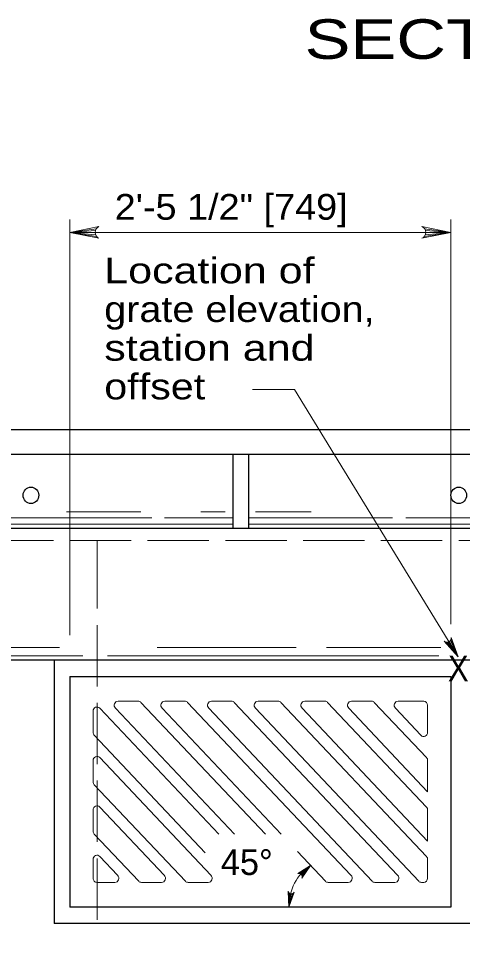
# Model space of a CAD drawing. Extents: x 1352.5 to 1386.5, y 735.9 to 779.9.
# Drawn here: x 1360.33 to 1363.03, y 762.99 to 768.66 of the extents above; entities that cross this region are included whole.
import ezdxf
from ezdxf.enums import TextEntityAlignment as Align

# ---------------------------------------------------------------- set-up
doc = ezdxf.new("R2010")
doc.units = 0
doc.header["$LTSCALE"] = 0.062
doc.linetypes.add('LONG_DASHED', pattern=[7.5, 6, -1.5])
doc.layers.add('1', color=7, linetype='Continuous', lineweight=13)

msp = doc.modelspace()

# ---------------------------------------------------------------- linework, layer by layer
at = {"layer": '1'}
for p, q in [((1360.64467, 764.92325), (1360.64467, 767.44517)), ((1362.9575, 764.99033), (1362.9575, 767.44517)), ((1360.80492, 767.38892), (1360.64467, 767.3665)), ((1360.7995, 767.37783), (1360.64467, 767.3665)), ((1362.79725, 767.38892), (1362.9575, 767.3665)), ((1362.80267, 767.37783), (1362.9575, 767.3665)), ((1360.64467, 767.3665), (1362.10425, 767.3665)), ((1360.79783, 767.3665), (1360.64467, 767.3665)), ((1360.80067, 767.35217), (1360.64467, 767.3665)), ((1360.80683, 767.34175), (1360.64467, 767.3665)), ((1362.10425, 767.3665), (1362.9575, 767.3665)), ((1362.79533, 767.34175), (1362.9575, 767.3665)), ((1362.8015, 767.35217), (1362.9575, 767.3665)), ((1362.80433, 767.3665), (1362.9575, 767.3665)), ((1360.62375, 765.672), (1361.07475, 765.672)), ((1361.43867, 765.672), (1361.58725, 765.672)), ((1361.77183, 765.672), (1362.11008, 765.672)), ((1360.17267, 765.63458), (1361.14133, 765.63458)), ((1361.21833, 765.63458), (1361.63583, 765.63458)), ((1361.73025, 765.63458), (1362.60208, 765.63458)), ((1362.68408, 765.63458), (1364.27908, 765.63458)), ((1360.17267, 765.59708), (1361.63583, 765.59708)), ((1361.73025, 765.59708), (1364.27908, 765.59708)), ((1362.9305, 764.88142), (1363.0005, 764.79217)), ((1362.93908, 764.88158), (1363.0005, 764.79217)), ((1362.94642, 764.88425), (1363.0005, 764.79217)), ((1362.95408, 764.89042), (1363.0005, 764.79217)), ((1362.95808, 764.89733), (1363.0005, 764.79217)), ((1359.91117, 764.8475), (1360.5815, 764.8475)), ((1361.17508, 764.8475), (1362.018, 764.8475)), ((1362.20208, 764.8475), (1362.89667, 764.8475)), ((1358.72892, 764.7975), (1360.724, 764.7975)), ((1360.87233, 764.7975), (1362.88475, 764.7975)), ((1361.54892, 763.71533), (1360.82658, 764.48008)), ((1361.64325, 763.71533), (1360.92092, 764.48008)), ((1360.93767, 764.52267), (1361.05975, 764.52267)), ((1361.83208, 763.71533), (1361.07642, 764.51533)), ((1361.92642, 763.71533), (1361.20417, 764.48008)), ((1361.22083, 764.52267), (1361.34292, 764.52267)), ((1362.35083, 763.466), (1361.35958, 764.51533)), ((1362.47858, 763.43067), (1361.48733, 764.48008)), ((1361.504, 764.52267), (1361.62608, 764.52267)), ((1362.634, 763.466), (1361.64283, 764.51533)), ((1362.76175, 763.43067), (1361.77058, 764.48008)), ((1361.78725, 764.52267), (1361.90933, 764.52267)), ((1362.80892, 763.58058), (1361.926, 764.51533)), ((1362.81583, 763.67317), (1362.05375, 764.48008)), ((1362.07042, 764.52267), (1362.1925, 764.52267)), ((1362.80892, 763.88042), (1362.20917, 764.51533)), ((1362.81583, 763.97308), (1362.33692, 764.48008)), ((1362.35367, 764.52267), (1362.47575, 764.52267)), ((1362.80892, 764.18025), (1362.49242, 764.51533)), ((1362.77558, 764.3155), (1362.62017, 764.48008)), ((1362.79225, 764.52267), (1362.63683, 764.52267)), ((1362.81583, 764.33317), (1362.81583, 764.49767)), ((1360.78625, 764.33317), (1360.78625, 764.46242)), ((1361.46625, 763.60292), (1360.79317, 764.3155)), ((1360.78625, 764.03333), (1360.78625, 764.16258)), ((1361.50117, 763.466), (1360.82658, 764.18025)), ((1362.81583, 763.97308), (1362.81583, 764.16258)), ((1361.34575, 763.43067), (1360.79317, 764.01567)), ((1360.78625, 763.7335), (1360.78625, 763.86275)), ((1361.218, 763.466), (1360.82658, 763.88042)), ((1362.81583, 763.67317), (1362.81583, 763.86275)), ((1361.06258, 763.43067), (1360.79317, 763.71583)), ((1360.93483, 763.466), (1360.82658, 763.58058)), ((1362.19533, 763.43067), (1362.02608, 763.60983)), ((1360.78625, 763.56292), (1360.78625, 763.44833)), ((1362.037, 763.47767), (1362.10475, 763.52658)), ((1362.04283, 763.47583), (1362.10475, 763.52658)), ((1362.04875, 763.47133), (1362.10475, 763.52658)), ((1362.052, 763.46633), (1362.10475, 763.52658)), ((1362.05383, 763.46017), (1362.10475, 763.52658)), ((1362.81583, 763.44833), (1362.81583, 763.56292)), ((1360.91808, 763.42333), (1360.80983, 763.42333)), ((1361.07925, 763.42333), (1361.20133, 763.42333)), ((1361.36242, 763.42333), (1361.4845, 763.42333)), ((1362.212, 763.42333), (1362.33408, 763.42333)), ((1362.49525, 763.42333), (1362.61733, 763.42333)), ((1362.77842, 763.42333), (1362.79225, 763.42333)), ((1361.97508, 763.359), (1361.97325, 763.27342)), ((1361.9985, 763.356), (1361.97325, 763.27342)), ((1361.98008, 763.35525), (1361.97325, 763.27342)), ((1361.99292, 763.35367), (1361.97325, 763.27342)), ((1361.98567, 763.35342), (1361.97325, 763.27342))]:
    msp.add_line(p, q, dxfattribs=at)
at = {"layer": '1', "lineweight": 25}
for p, q in [((1360.17267, 766.17175), (1365.83667, 766.17175)), ((1360.17267, 766.02183), (1365.83667, 766.02183)), ((1361.63583, 765.57208), (1361.63583, 766.02183)), ((1361.73025, 765.57208), (1361.73025, 766.02183)), ((1360.17267, 765.57208), (1365.83667, 765.57208)), ((1358.29033, 764.77258), (1364.77742, 764.77258)), ((1360.64467, 764.67258), (1360.64467, 763.27342)), ((1360.64467, 764.67258), (1362.9575, 764.67258)), ((1362.9575, 763.27342), (1360.64467, 763.27342))]:
    msp.add_line(p, q, dxfattribs=at)
at = {"layer": '1', "linetype": 'LONG_DASHED'}
msp.add_line((1360.17267, 765.49717), (1365.83667, 765.49717), dxfattribs=at)
at = {"layer": '1'}
for points in [[(1360.82167, 767.33108), (1360.64467, 767.3665), (1360.82167, 767.40192)], [(1362.7805, 767.33108), (1362.9575, 767.3665), (1362.7805, 767.40192)], [(1363.0005, 764.79217), (1362.00858, 766.413), (1361.75267, 766.413)], [(1362.95925, 764.90967), (1363.0005, 764.79217), (1362.91675, 764.88742)], [(1362.02783, 763.47642), (1362.10475, 763.52658), (1362.05208, 763.44908)], [(1362.00508, 763.36283), (1361.97325, 763.27342), (1361.97008, 763.36883)]]:
    msp.add_lwpolyline(points, dxfattribs=at)
at = {"layer": '1', "linetype": 'LONG_DASHED'}
msp.add_lwpolyline([(1360.80983, 765.49717), (1360.80983, 765.4565), (1360.80983, 763.1735)], dxfattribs=at)
at = {"layer": '1', "lineweight": 25}
for points in [[(1360.55025, 764.77258), (1360.55025, 763.81325), (1360.55025, 763.1735)], [(1362.9575, 764.67258), (1362.9575, 764.10783), (1362.9575, 763.27342)], [(1365.45908, 763.1735), (1363.63192, 763.1735), (1360.55025, 763.1735)]]:
    msp.add_lwpolyline(points, dxfattribs=at)
at = {"layer": '1'}
for centre, start, end in [((1360.83597, 767.36656), 112.08782, 247.91395), ((1362.76618, 767.36656), 292.08605, 67.91218)]:
    msp.add_arc(centre, 0.0382, start, end, dxfattribs=at)
at = {"layer": '1', "lineweight": 25}
for centre in [(1360.40867, 765.77197), (1363.00467, 765.77197)]:
    msp.add_ellipse(centre, major_axis=(0, 0.04997), ratio=0.944544, dxfattribs=at)
at = {"layer": '1'}
for centre, major_axis, start_param, end_param in [((1362.93293, 764.90715), (-0.0229, 0.01423), 1.4490743, 3.8196874), ((1360.80987, 764.46237), (0, 0.02499), 5.4977871, 7.8539816), ((1360.93765, 764.4977), (0, -0.02499), 3.1415927, 5.4977871), ((1361.0597, 764.4977), (0, 0.02499), 5.4977871, 6.2831853), ((1361.22085, 764.4977), (0, -0.02499), 3.1415927, 5.4977871), ((1361.3429, 764.4977), (0, 0.02499), 5.4977871, 6.2831853), ((1361.50405, 764.4977), (0, -0.02499), 3.1415927, 5.4977871), ((1361.6261, 764.4977), (0, 0.02499), 5.4977871, 6.2831853), ((1361.78725, 764.4977), (0, -0.02499), 3.1415927, 5.4977871), ((1361.9093, 764.4977), (0, 0.02499), 5.4977871, 6.2831853), ((1362.07045, 764.4977), (0, -0.02499), 3.1415927, 5.4977871), ((1362.1925, 764.4977), (0, 0.02499), 5.4977871, 6.2831853), ((1362.35366, 764.4977), (0, -0.02499), 3.1415927, 5.4978629), ((1362.4757, 764.4977), (0, 0.02499), 5.4977871, 6.2831853), ((1362.63685, 764.4977), (0, -0.02499), 3.1415927, 5.4977871), ((1362.79227, 764.4977), (0, 0.02499), 4.712389, 6.2831853), ((1360.80987, 764.33315), (0, 0.02499), 1.5707963, 2.3561945), ((1362.79227, 764.33315), (0, -0.02499), 5.4977871, 7.8539816), ((1360.80987, 764.16254), (0, 0.02499), 5.4977871, 7.8539816), ((1362.79227, 764.16254), (0, 0.02499), 4.712389, 5.4977871), ((1360.80987, 764.03333), (0, 0.02499), 1.5707963, 2.3561945), ((1360.80987, 763.86271), (0, 0.02499), 5.4977871, 7.8539816), ((1362.79227, 763.86271), (0, 0.02499), 4.712389, 5.4977871), ((1360.80987, 763.7335), (0, 0.02499), 1.5707963, 2.3561945), ((1360.80987, 763.56289), (0, 0.02499), 5.4977871, 7.8539816), ((1362.79227, 763.56289), (0, 0.02499), 4.712389, 5.4977871), ((1362.25647, 763.27341), (0, 0.29983), 0.565407, 1.5707963), ((1360.9181, 763.44831), (0, -0.02499), 6.2831853, 8.6393798), ((1361.2013, 763.44831), (0, -0.02499), 6.2831853, 8.6393798), ((1361.4845, 763.44831), (0, -0.02499), 6.2831853, 8.6393798), ((1362.03475, 763.45751), (0, -0.02022), 1.1360379, 3.506651), ((1362.3341, 763.44831), (0, -0.02499), 6.2831853, 8.6393798), ((1362.6173, 763.44831), (0, -0.02499), 6.2831853, 8.6393798), ((1360.80987, 763.44831), (0, 0.02499), 1.5707963, 3.1415927), ((1361.07925, 763.44831), (0, -0.02499), 5.4977871, 6.2831853), ((1361.36245, 763.44831), (0, -0.02499), 5.4977871, 6.2831853), ((1362.21205, 763.44831), (0, -0.02499), 5.4977871, 6.2831853), ((1362.49525, 763.44831), (0, -0.02499), 5.4977871, 6.2831853), ((1362.77845, 763.44831), (0, -0.02499), 5.4977871, 6.2831853), ((1362.79227, 763.44831), (0, 0.02499), 3.1415927, 4.712389), ((1361.98869, 763.37339), (0, -0.02022), 4.936031, 7.3066441)]:
    msp.add_ellipse(centre, major_axis=major_axis, ratio=0.944544, start_param=start_param, end_param=end_param, dxfattribs=at)
at = {"layer": '1', "lineweight": 25}
msp.add_spline([(1358.28467, 765.17233), (1358.27392, 765.12667), (1358.2975, 765.03625), (1358.28183, 764.97875), (1358.263, 764.8895), (1358.2955, 764.75042), (1358.29975, 764.70767), (1358.27567, 764.65417), (1358.30367, 764.527), (1358.276, 764.413), (1358.29917, 764.27292), (1358.27708, 764.15292), (1358.308, 764.03467), (1358.2615, 763.91375), (1358.30475, 763.80333), (1358.30933, 763.79042), (1358.28633, 763.67242), (1358.307, 763.56908), (1358.30733, 763.5055), (1358.26458, 763.39358), (1358.2765, 763.35383), (1358.31542, 763.28217), (1358.33125, 763.166), (1358.2845, 763.03125), (1358.26858, 762.95183), (1358.2935, 762.80483), (1358.2925, 762.70558), (1358.27417, 762.57167), (1358.29075, 762.43958), (1358.27958, 762.36417), (1358.30842, 762.236), (1358.29917, 762.16067), (1358.29425, 762.13983), (1358.30233, 762.00375), (1358.26642, 761.91058), (1358.28425, 761.722), (1358.26283, 761.65158), (1358.28, 761.586), (1358.3085, 761.50242), (1358.29175, 761.34075), (1358.2805, 761.25842), (1358.29475, 761.17592), (1358.35658, 761.13), (1358.51342, 761.13717), (1358.55292, 761.12108), (1358.56608, 761.11508), (1358.63575, 761.09783), (1358.76925, 761.133), (1358.85692, 761.11367), (1358.89675, 761.13533), (1358.97408, 761.129), (1359.03258, 761.11875), (1359.12533, 761.14317), (1359.181, 761.13592), (1359.29192, 761.09167), (1359.431, 761.11583), (1359.51567, 761.08167), (1359.62733, 761.11192), (1359.73958, 761.09942), (1359.86158, 761.11775), (1359.87758, 761.11667), (1359.968, 761.08742), (1360.04842, 761.10192), (1360.08075, 761.12558), (1360.16192, 761.12125), (1360.21442, 761.09217), (1360.28625, 761.09775), (1360.36108, 761.11825), (1360.50533, 761.09767), (1360.6295, 761.13883), (1360.74825, 761.12333), (1360.84658, 761.13875), (1360.96342, 761.10742), (1361.01933, 761.13), (1361.08833, 761.13558), (1361.15683, 761.0975), (1361.255, 761.08808), (1361.27867, 761.09392), (1361.43375, 761.122), (1361.49517, 761.11967), (1361.53275, 761.10167), (1361.57025, 761.08258), (1361.784, 761.11633), (1361.85842, 761.09508), (1362.07767, 761.11092), (1362.13883, 761.09375), (1362.31467, 761.11475), (1362.37792, 761.11242), (1362.4625, 761.07225), (1362.54092, 761.07883), (1362.56267, 761.08175), (1362.68658, 761.099), (1362.80325, 761.06467), (1363.02833, 761.09833), (1363.14808, 761.08083), (1363.22175, 761.07458), (1363.42808, 761.12617)], degree=3, dxfattribs=at)

# ---------------------------------------------------------------- texts
at = {"layer": '1'}
for s, height, width, p in [('SECTION A-A', 0.24, 1.3, (1362.06925, 768.42)), ('2\'-5 1/2" [749]', 0.156, 1.1, (1360.91683, 767.44392)), ('Location of', 0.156, 1.25, (1360.85375, 767.058)), ('grate elevation,', 0.156, 1.15, (1360.85375, 766.82333)), ('station and', 0.156, 1.25, (1360.85375, 766.58867)), ('offset', 0.156, 1.2, (1360.85375, 766.354))]:
    msp.add_text(s, height=height, dxfattribs=dict(at, width=width)).set_placement(p)
at = {"layer": '1', "width": 0.9}
msp.add_text('X', height=0.156, dxfattribs=at).set_placement((1363.00192, 764.64367), align=Align.CENTER)
at = {"layer": '1'}
msp.add_text('45°', height=0.156, dxfattribs=at).set_placement((1361.56058, 763.46808))

doc.saveas('drawing.dxf')
